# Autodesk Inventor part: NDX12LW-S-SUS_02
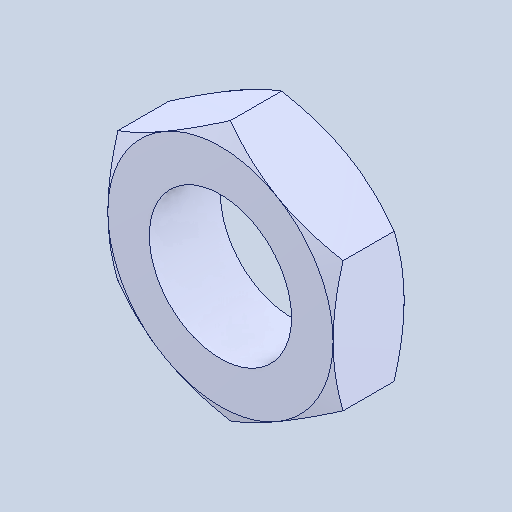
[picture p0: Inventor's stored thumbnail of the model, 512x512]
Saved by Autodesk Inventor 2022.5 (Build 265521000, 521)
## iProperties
Created: 2024-05
Part Number: NDX12LW-S-SUS_02
Material: 一般
Document SubType Name: Modeling
Designer: ImaoCorp
Density: 1 g/cm^3
Appearance: 既定
Author: ImaoCorp
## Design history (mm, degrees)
feature "NDX12LW-S-SUS_02"
node "ソリッド1"
